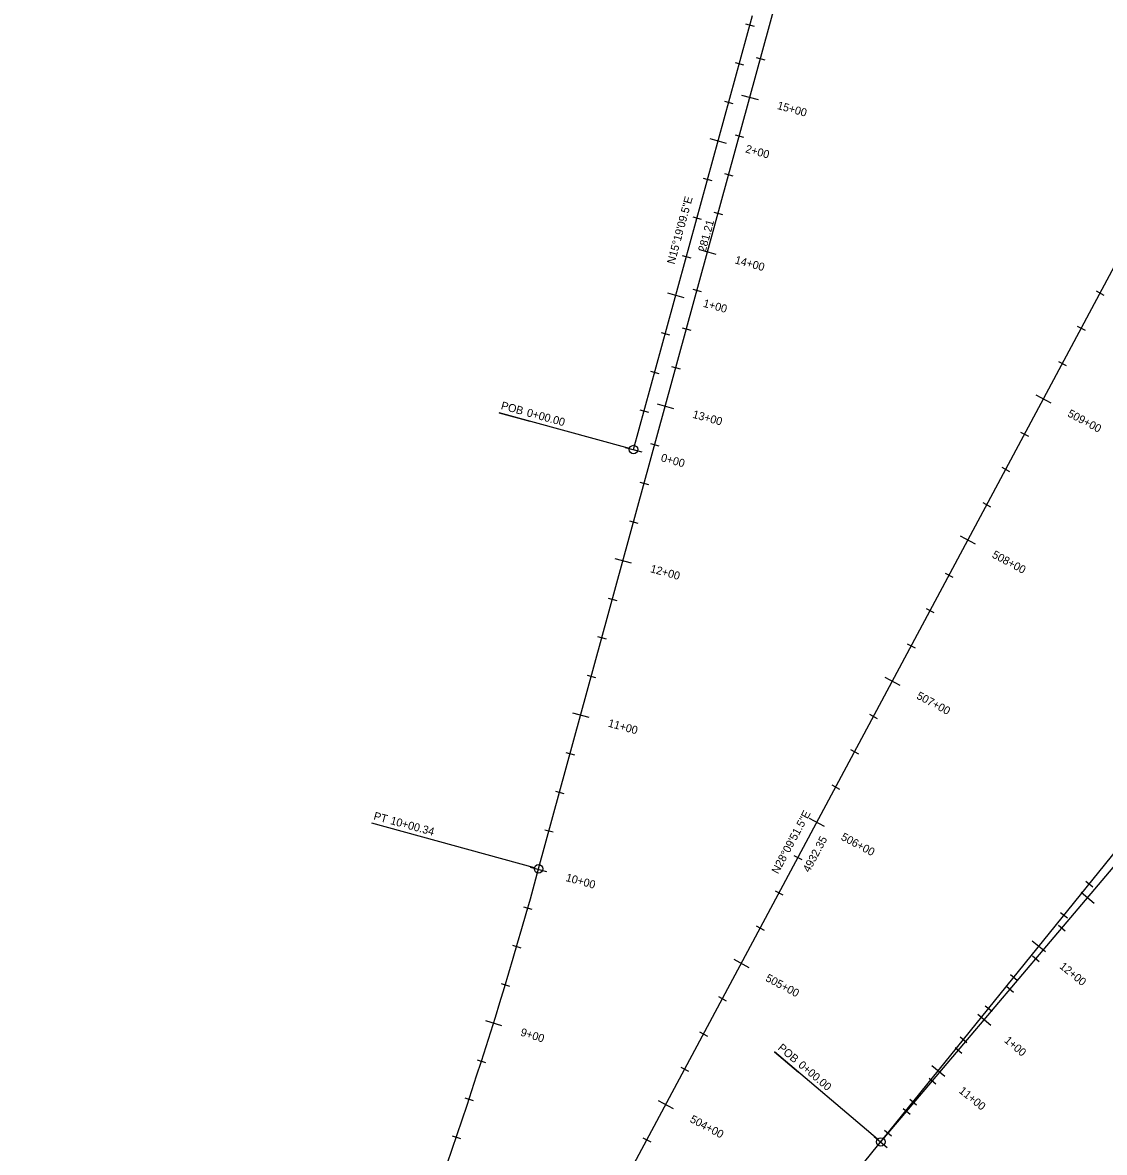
# Model space of a CAD drawing. Extents: x 2300830 to 2307917, y 756066 to 766359.
# Drawn here: x 2302145 to 2302821, y 759600 to 760306 of the extents above; entities that cross this region are included whole.
import ezdxf

# ---------------------------------------------------------------- set-up
doc = ezdxf.new("R2010")
doc.units = 0
for name, color, linetype in [('Default', 7, 'Continuous'), ('Draft_Bearing Label', 7, 'Continuous'), ('Draft_Station Cardinal Lines', 7, 'Continuous'), ('Draft_Station Cardinal Points', 7, 'Continuous'), ('Draft_Station Labels Major', 7, 'Continuous'), ('Draft_Station Ticks Major', 7, 'Continuous'), ('Draft_Station Ticks Minor', 7, 'Continuous'), ('Geom_Baseline', 7, 'Continuous')]:
    doc.layers.add(name, color=color, linetype=linetype)

msp = doc.modelspace()

# ---------------------------------------------------------------- linework, layer by layer
at = {"layer": 'Default'}
for p, q in [((2301469.01, 757616.61), (2303797.09, 761964.97)), ((2301469.01, 757616.61), (2303797.09, 761964.97)), ((2302467.58, 759777.24), (2302927, 761454.36)), ((2302671.51, 759594.38), (2303742.71, 760919.55)), ((2302526.92, 760039.15), (2302601.22, 760310.37)), ((2302681.45, 759606.69), (2303023.05, 760010.24))]:
    msp.add_line(p, q, dxfattribs=at)
msp.add_arc((2299700.87, 760535.13), 2868.64, 332.35668, 344.6807, dxfattribs=at)
at = {"layer": 'Draft_Station Cardinal Lines'}
msp.add_line((2302465.01, 759777.95), (2302363.42, 759805.77), dxfattribs=at)
at = {"layer": 'Draft_Station Cardinal Points'}
for p, q in [((2302524.35, 760039.85), (2302443.01, 760062.13)), ((2302443.01, 760062.13), (2302461.99, 760056.93)), ((2302526.92, 760039.15), (2302526.92, 760039.15)), ((2302363.42, 759805.77), (2302363.42, 759805.77)), ((2302467.58, 759777.24), (2302467.58, 759777.24)), ((2302679.42, 759608.41), (2302615.05, 759662.89)), ((2302615.05, 759662.89), (2302630.07, 759650.18)), ((2302681.45, 759606.69), (2302681.45, 759606.69))]:
    msp.add_line(p, q, dxfattribs=at)
for centre in [(2302526.92, 760039.15), (2302467.58, 759777.24), (2302681.45, 759606.69)]:
    msp.add_circle(centre, 2.67, dxfattribs=at)
at = {"layer": 'Draft_Station Ticks Major'}
for p, q in [((2302594.44, 760260.56), (2302604.69, 760257.75)), ((2302574.61, 760233.45), (2302584.85, 760230.65)), ((2302568.02, 760164.11), (2302578.27, 760161.31)), ((2302548.19, 760137.01), (2302558.43, 760134.2)), ((2302541.6, 760067.66), (2302551.85, 760064.86)), ((2302778.3, 760073.4), (2302787.67, 760068.39)), ((2302521.77, 760040.56), (2302532.01, 760037.75)), ((2302731.1, 759985.24), (2302740.47, 759980.23)), ((2302515.18, 759971.22), (2302525.43, 759968.41)), ((2302683.9, 759897.08), (2302693.26, 759892.07)), ((2302488.76, 759874.77), (2302499.01, 759871.97)), ((2302636.7, 759808.92), (2302646.06, 759803.91)), ((2302462.34, 759778.32), (2302472.59, 759775.52)), ((2302806.6, 759762.79), (2302814.7, 759755.93)), ((2302776.1, 759732.26), (2302784.36, 759725.58)), ((2302589.5, 759720.76), (2302598.86, 759715.75)), ((2302741.99, 759686.46), (2302750.09, 759679.6)), ((2302434.29, 759682.54), (2302444.43, 759679.38)), ((2302713.23, 759654.49), (2302721.49, 759647.82)), ((2302542.3, 759632.6), (2302551.66, 759627.59)), ((2302677.38, 759610.14), (2302685.48, 759603.27))]:
    msp.add_line(p, q, dxfattribs=at)
at = {"layer": 'Draft_Station Ticks Minor'}
for p, q in [((2302596.91, 760305.11), (2302602.24, 760303.65)), ((2302590.31, 760280.99), (2302595.63, 760279.54)), ((2302603.54, 760283.99), (2302608.86, 760282.53)), ((2302583.7, 760256.88), (2302589.03, 760255.42)), ((2302590.33, 760235.77), (2302595.65, 760234.31)), ((2302570.49, 760208.66), (2302575.82, 760207.2)), ((2302583.72, 760211.65), (2302589.04, 760210.19)), ((2302577.12, 760187.54), (2302582.44, 760186.08)), ((2302563.89, 760184.55), (2302569.21, 760183.09)), ((2302557.28, 760160.44), (2302562.61, 760158.98)), ((2302563.91, 760139.32), (2302569.23, 760137.86)), ((2302815.98, 760138.3), (2302820.84, 760135.7)), ((2302544.07, 760112.21), (2302549.4, 760110.75)), ((2302557.3, 760115.21), (2302562.62, 760113.75)), ((2302804.18, 760116.26), (2302809.04, 760113.66)), ((2302550.7, 760091.09), (2302556.02, 760089.64)), ((2302792.38, 760094.22), (2302797.24, 760091.62)), ((2302537.47, 760088.1), (2302542.79, 760086.64)), ((2302530.86, 760063.99), (2302536.19, 760062.53)), ((2302768.78, 760050.14), (2302773.64, 760047.54)), ((2302537.49, 760042.87), (2302542.81, 760041.41)), ((2302756.98, 760028.1), (2302761.84, 760025.5)), ((2302530.88, 760018.76), (2302536.21, 760017.3)), ((2302745.18, 760006.06), (2302750.04, 760003.46)), ((2302524.28, 759994.65), (2302529.6, 759993.19)), ((2302721.58, 759961.98), (2302726.44, 759959.38)), ((2302511.07, 759946.42), (2302516.39, 759944.97)), ((2302709.78, 759939.94), (2302714.64, 759937.34)), ((2302504.46, 759922.31), (2302509.79, 759920.85)), ((2302697.98, 759917.9), (2302702.84, 759915.3)), ((2302497.86, 759898.2), (2302503.18, 759896.74)), ((2302674.38, 759873.82), (2302679.24, 759871.22)), ((2302484.65, 759849.98), (2302489.97, 759848.52)), ((2302662.58, 759851.78), (2302667.44, 759849.18)), ((2302650.78, 759829.74), (2302655.64, 759827.14)), ((2302478.04, 759825.87), (2302483.37, 759824.41)), ((2302471.44, 759801.75), (2302476.76, 759800.3)), ((2302627.18, 759785.66), (2302632.04, 759783.06)), ((2302809.54, 759769.52), (2302813.83, 759766.05)), ((2302615.38, 759763.62), (2302620.24, 759761.02)), ((2302458.13, 759753.58), (2302463.44, 759752.08)), ((2302793.82, 759750.08), (2302798.11, 759746.61)), ((2302603.58, 759741.58), (2302608.44, 759738.98)), ((2302792.41, 759742.04), (2302796.63, 759738.47)), ((2302451.21, 759729.58), (2302456.51, 759728.03)), ((2302776.26, 759722.96), (2302780.47, 759719.39)), ((2302762.39, 759711.2), (2302766.68, 759707.73)), ((2302444.09, 759705.65), (2302449.37, 759704.05)), ((2302760.11, 759703.88), (2302764.32, 759700.31)), ((2302579.98, 759697.5), (2302584.84, 759694.9)), ((2302746.67, 759691.75), (2302750.96, 759688.28)), ((2302568.18, 759675.46), (2302573.04, 759672.86)), ((2302730.95, 759672.31), (2302735.25, 759668.84)), ((2302727.8, 759665.71), (2302732.02, 759662.15)), ((2302429.21, 759657.96), (2302434.47, 759656.27)), ((2302556.38, 759653.42), (2302561.24, 759650.82)), ((2302711.65, 759646.63), (2302715.87, 759643.07)), ((2302421.46, 759634.22), (2302426.7, 759632.48)), ((2302699.52, 759633.43), (2302703.82, 759629.96)), ((2302695.5, 759627.55), (2302699.71, 759623.98)), ((2302413.51, 759610.54), (2302418.73, 759608.76)), ((2302532.78, 759609.34), (2302537.64, 759606.74)), ((2302683.81, 759613.99), (2302688.1, 759610.52))]:
    msp.add_line(p, q, dxfattribs=at)
at = {"layer": 'Geom_Baseline'}
for p, q in [((2301469.01, 757616.61), (2303797.09, 761964.97)), ((2302467.58, 759777.24), (2302927, 761454.36)), ((2302671.51, 759594.38), (2303742.71, 760919.55)), ((2302526.92, 760039.15), (2302601.22, 760310.37)), ((2302681.45, 759606.69), (2303023.05, 760010.24))]:
    msp.add_line(p, q, dxfattribs=at)
msp.add_arc((2299700.87, 760535.13), 2868.64, 332.35668, 344.6807, dxfattribs=at)

# ---------------------------------------------------------------- texts
at = {"layer": 'Draft_Bearing Label'}
for s, rotation, p in [('N15°19\'09.5"E', 74.6807, (2302552.44, 760154.58)), ('281.21', 74.6807, (2302571.91, 760162.2)), ('N28°09\'51.5"E', 61.8357, (2302617.23, 759773.7)), ('4932.35', 61.8357, (2302636.75, 759774.65))]:
    msp.add_text(s, height=5, rotation=rotation, dxfattribs=at).set_placement(p)
at = {"layer": 'Draft_Station Cardinal Points'}
for s, rotation, p in [('POB ', 344.6807, (2302443.67, 760064.53)), ('0+00.00', 344.6807, (2302459.77, 760060.12)), ('PT', 344.6807, (2302364.08, 759808.17)), ('10+00.34', 344.6807, (2302374.56, 759805.3)), ('POB ', 319.75294, (2302616.66, 759664.79)), ('0+00.00', 319.75294, (2302629.4, 759654))]:
    msp.add_text(s, height=5, rotation=rotation, dxfattribs=at).set_placement(p)
at = {"layer": 'Draft_Station Labels Major'}
for s, rotation, p in [('15+00', 344.6807, (2302616.29, 760251.98)), ('2+00', 344.6807, (2302596.46, 760224.87)), ('14+00', 344.6807, (2302589.87, 760155.53)), ('1+00', 344.6807, (2302570.04, 760128.43)), ('13+00', 344.6807, (2302563.45, 760059.09)), ('509+00', 331.8357, (2302797.7, 760060.18)), ('0+00', 344.6807, (2302543.62, 760031.98)), ('508+00', 331.8357, (2302750.5, 759972.02)), ('12+00', 344.6807, (2302537.03, 759962.64)), ('507+00', 331.8357, (2302703.3, 759883.86)), ('11+00', 344.6807, (2302510.61, 759866.19)), ('506+00', 331.8357, (2302656.1, 759795.7)), ('10+00', 344.67393, (2302484.19, 759769.74)), ('12+00', 321.04981, (2302792.68, 759715.64)), ('505+00', 331.8357, (2302608.9, 759707.54)), ('9+00', 342.67661, (2302455.83, 759673.2)), ('1+00', 319.75294, (2302758.19, 759669.47)), ('11+00', 321.04981, (2302729.81, 759637.88)), ('504+00', 331.8357, (2302561.7, 759619.38))]:
    msp.add_text(s, height=5, rotation=rotation, dxfattribs=at).set_placement(p)

doc.saveas('drawing.dxf')
